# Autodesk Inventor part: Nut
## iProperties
Shininess: 77.0
Length Units: 11269
Angle Units: 11279
Time Units: 11290
Mass Units: 11283
Length Display Precision: 3
Angle Display Precision: 2
Created: 2002-02
Part Number: Nut
Document SubType Name: Modeling
Designer: ***
Stock Number: 02
Density: 0.0
Volumn: 0.0
Area: 0.0
PropertySet Name: Model Information
Control State: 0
Master: False
Checked Out: False
Author: ***
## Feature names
1. Extrusion1
2. Fillet1
3. Extrusion2
4. Hole1
